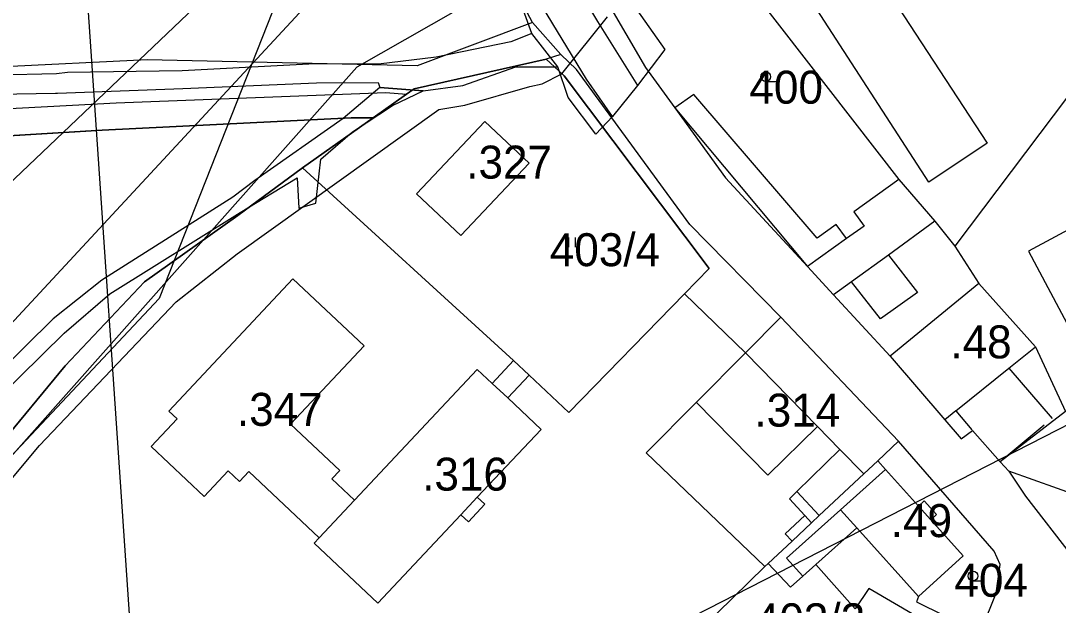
# Model space of a CAD drawing. Extents: x -564810 to -550519, y -1045831 to -1034011.
# Drawn here: x -553559.2 to -553398.7, y -1036821.1 to -1036730.6 of the extents above; entities that cross this region are included whole.
import ezdxf

# ---------------------------------------------------------------- set-up
doc = ezdxf.new("R2010")
doc.units = 0
for name, color, linetype in [('KN stav', 7, 'Continuous'), ('Obvod KPU', 7, 'Continuous'), ('Parcelní čísla', 7, 'Continuous'), ('Plynovod', 7, 'Continuous'), ('Polní cesty stavající', 7, 'Continuous'), ('STG', 7, 'Continuous'), ('Vedení VN', 7, 'Continuous'), ('Vrstva 16', 7, 'Continuous'), ('Vrstva 22', 7, 'Continuous'), ('Vrstva 39', 7, 'Continuous'), ('Vrstva 4', 7, 'Continuous'), ('zamokř ploch', 7, 'Continuous')]:
    doc.layers.add(name, color=color, linetype=linetype)

msp = doc.modelspace()

# ---------------------------------------------------------------- linework, layer by layer
at = {"layer": 'KN stav'}
for p, q in [((-553480, -1036730.9), (-553506.43, -1036681.97)), ((-553453.94, -1036715.78), (-553423.34, -1036755.23)), ((-553468.61, -1036727.47), (-553462.54, -1036737.9)), ((-553480, -1036730.9), (-553497.88, -1036737.61)), ((-553475.61, -1036735.89), (-553480, -1036730.9)), ((-553390.79, -1036733.87), (-553414.68, -1036765.53)), ((-553539.67, -1036736.67), (-553646.49, -1036742.01)), ((-553497.88, -1036737.61), (-553539.67, -1036736.67)), ((-553477.9, -1036736.58), (-553498.31, -1036741.16)), ((-553498.31, -1036741.16), (-553477.9, -1036736.58)), ((-553475.61, -1036735.89), (-553477.9, -1036736.58)), ((-553477.9, -1036736.58), (-553475.25, -1036739)), ((-553475.25, -1036739), (-553477.9, -1036736.58)), ((-553473.22, -1036738.18), (-553475.61, -1036735.89)), ((-553475.25, -1036739), (-553475.13, -1036739.16)), ((-553475.13, -1036739.16), (-553475.25, -1036739)), ((-553455.66, -1036762.18), (-553473.22, -1036738.18)), ((-553462.54, -1036737.9), (-553458, -1036744.14)), ((-553475.13, -1036739.16), (-553452.69, -1036769)), ((-553452.69, -1036769), (-553475.13, -1036739.16)), ((-553544.43, -1036743.37), (-553502.71, -1036741.75)), ((-553499.51, -1036742.01), (-553504.68, -1036745.67)), ((-553504.68, -1036745.67), (-553499.51, -1036742.01)), ((-553502.71, -1036741.75), (-553499.51, -1036742.01)), ((-553498.31, -1036741.16), (-553499.51, -1036742.01)), ((-553499.51, -1036742.01), (-553498.31, -1036741.16)), ((-553455.05, -1036742.06), (-553458, -1036744.14)), ((-553435.95, -1036764.27), (-553455.05, -1036742.06)), ((-553598.13, -1036746.15), (-553544.43, -1036743.37)), ((-553458, -1036744.14), (-553450.14, -1036754.96)), ((-553546.63, -1036747.58), (-553508.07, -1036745.65)), ((-553508.07, -1036745.65), (-553546.63, -1036747.58)), ((-553504.68, -1036745.67), (-553515.6, -1036753.41)), ((-553515.6, -1036753.41), (-553504.68, -1036745.67)), ((-553508.07, -1036745.65), (-553504.68, -1036745.67)), ((-553504.68, -1036745.67), (-553508.07, -1036745.65)), ((-553487.42, -1036746.22), (-553497.96, -1036757.4)), ((-553497.96, -1036757.4), (-553487.42, -1036746.22)), ((-553480.55, -1036752.7), (-553487.42, -1036746.22)), ((-553487.42, -1036746.22), (-553480.55, -1036752.7)), ((-553583.22, -1036749.82), (-553546.63, -1036747.58)), ((-553546.63, -1036747.58), (-553583.22, -1036749.82)), ((-553515.6, -1036753.41), (-553525.6, -1036760.76)), ((-553525.6, -1036760.76), (-553515.6, -1036753.41)), ((-553482.96, -1036783.22), (-553515.6, -1036753.41)), ((-553515.6, -1036753.41), (-553482.96, -1036783.22)), ((-553491.09, -1036763.88), (-553480.55, -1036752.7)), ((-553480.55, -1036752.7), (-553491.09, -1036763.88)), ((-553450.14, -1036754.96), (-553437.47, -1036768.69)), ((-553423.34, -1036755.23), (-553430.29, -1036760.21)), ((-553423.34, -1036755.23), (-553417.77, -1036761.65)), ((-553497.96, -1036757.4), (-553491.09, -1036763.88)), ((-553491.09, -1036763.88), (-553497.96, -1036757.4)), ((-553525.6, -1036760.76), (-553540.04, -1036771.06)), ((-553540.04, -1036771.06), (-553525.6, -1036760.76)), ((-553430.29, -1036760.21), (-553428.71, -1036762.41)), ((-553441.6, -1036776.51), (-553455.66, -1036762.18)), ((-553433.01, -1036762.16), (-553435.95, -1036764.27)), ((-553431.44, -1036764.36), (-553433.01, -1036762.16)), ((-553428.71, -1036762.41), (-553431.44, -1036764.36)), ((-553417.77, -1036761.65), (-553414.68, -1036765.53)), ((-553414.68, -1036765.53), (-553410.95, -1036771.32)), ((-553452.69, -1036769), (-553456.51, -1036772.92)), ((-553456.51, -1036772.92), (-553452.69, -1036769)), ((-553437.47, -1036768.69), (-553433.44, -1036773.06)), ((-553540.04, -1036771.06), (-553552.36, -1036784.03)), ((-553552.36, -1036784.03), (-553540.04, -1036771.06)), ((-553536.32, -1036791.05), (-553517.1, -1036770.59)), ((-553517.1, -1036770.59), (-553506.08, -1036780.94)), ((-553410.95, -1036771.32), (-553402.2, -1036781.1)), ((-553456.51, -1036772.92), (-553474.39, -1036791.27)), ((-553474.39, -1036791.27), (-553456.51, -1036772.92)), ((-553433.44, -1036773.06), (-553424.68, -1036782.56)), ((-553447.06, -1036782.01), (-553441.6, -1036776.51)), ((-553423.36, -1036795.71), (-553441.6, -1036776.51)), ((-553506.08, -1036780.94), (-553517.46, -1036793.06)), ((-553454.66, -1036789.66), (-553447.06, -1036782.01)), ((-553402.2, -1036781.1), (-553397.52, -1036791.1)), ((-553552.36, -1036784.03), (-553589.87, -1036829.38)), ((-553589.87, -1036829.38), (-553552.36, -1036784.03)), ((-553486.28, -1036786.76), (-553482.96, -1036783.22)), ((-553480.56, -1036785.48), (-553482.96, -1036783.22)), ((-553482.96, -1036783.22), (-553480.56, -1036785.48)), ((-553424.68, -1036782.56), (-553416.21, -1036792.38)), ((-553507.56, -1036804.82), (-553488.57, -1036784.61)), ((-553488.57, -1036784.61), (-553486.28, -1036786.76)), ((-553480.56, -1036785.48), (-553483.86, -1036789)), ((-553474.39, -1036791.27), (-553480.56, -1036785.48)), ((-553480.56, -1036785.48), (-553474.39, -1036791.27)), ((-553483.86, -1036789), (-553478.68, -1036793.86)), ((-553462.44, -1036797.49), (-553454.66, -1036789.66)), ((-553535.03, -1036792.26), (-553536.32, -1036791.05)), ((-553397.52, -1036791.1), (-553407.66, -1036798.87)), ((-553539.04, -1036796.54), (-553535.03, -1036792.26)), ((-553517.46, -1036793.06), (-553509.83, -1036800.24)), ((-553416.21, -1036792.38), (-553413.66, -1036795.34)), ((-553478.68, -1036793.86), (-553488.56, -1036804.37)), ((-553413.66, -1036795.34), (-553411.92, -1036794.04)), ((-553411.92, -1036794.04), (-553407.66, -1036798.87)), ((-553530.83, -1036804.25), (-553539.04, -1036796.54)), ((-553423.36, -1036795.71), (-553426.58, -1036798.72)), ((-553408.57, -1036812.73), (-553423.36, -1036795.71)), ((-553444.08, -1036815.09), (-553462.44, -1036797.49)), ((-553426.58, -1036798.72), (-553428.74, -1036800.74)), ((-553426.58, -1036798.72), (-553425.38, -1036800.05)), ((-553425.38, -1036800.05), (-553420.28, -1036805.73)), ((-553407.66, -1036798.87), (-553406.3, -1036800.33)), ((-553527.11, -1036800.3), (-553530.83, -1036804.25)), ((-553525.36, -1036801.95), (-553527.11, -1036800.3)), ((-553523.9, -1036800.4), (-553525.36, -1036801.95)), ((-553513.01, -1036810.63), (-553523.9, -1036800.4)), ((-553509.83, -1036800.24), (-553511.05, -1036801.54)), ((-553511.05, -1036801.54), (-553507.56, -1036804.82)), ((-553428.74, -1036800.74), (-553435.66, -1036807.21)), ((-553406.3, -1036800.33), (-553403.71, -1036804.22)), ((-553391.72, -1036805.55), (-553406.3, -1036800.33)), ((-553507.56, -1036804.82), (-553513.01, -1036810.63)), ((-553488.56, -1036804.37), (-553487.4, -1036805.46)), ((-553403.71, -1036804.22), (-553396.47, -1036813.58)), ((-553487.4, -1036805.46), (-553489.94, -1036808.17)), ((-553420.28, -1036805.73), (-553419.39, -1036804.94)), ((-553419.39, -1036804.94), (-553417.48, -1036807.06)), ((-553491.1, -1036807.08), (-553503.95, -1036820.76)), ((-553489.94, -1036808.17), (-553491.1, -1036807.08)), ((-553435.66, -1036807.21), (-553436.82, -1036808.3)), ((-553417.48, -1036807.06), (-553418.37, -1036807.86)), ((-553418.37, -1036807.86), (-553413.35, -1036813.45)), ((-553436.82, -1036808.3), (-553439.86, -1036811.14)), ((-553513.82, -1036811.49), (-553513.01, -1036810.63)), ((-553439.86, -1036811.14), (-553443.55, -1036814.59)), ((-553503.95, -1036820.76), (-553513.82, -1036811.49)), ((-553407.66, -1036814.79), (-553408.57, -1036812.73)), ((-553413.35, -1036813.45), (-553420.31, -1036819.7)), ((-553454.68, -1036825.42), (-553444.08, -1036815.09)), ((-553443.55, -1036814.59), (-553444.08, -1036815.09)), ((-553443.55, -1036814.59), (-553440.09, -1036818.29)), ((-553438.2, -1036816.58), (-553436.18, -1036814.77)), ((-553436.18, -1036814.77), (-553430.09, -1036821.62)), ((-553408.24, -1036819.19), (-553407.66, -1036814.79)), ((-553440.09, -1036818.29), (-553438.2, -1036816.58)), ((-553427.97, -1036818.48), (-553430.09, -1036821.62)), ((-553411.77, -1036827.9), (-553427.97, -1036818.48)), ((-553410.74, -1036825.37), (-553408.24, -1036819.19)), ((-553420.31, -1036819.7), (-553420.59, -1036820.55)), ((-553420.59, -1036820.55), (-553410.74, -1036825.37))]:
    msp.add_line(p, q, dxfattribs=at)
at = {"layer": 'Obvod KPU'}
for p, q in [((-553475.47, -1036738.86), (-553468.39, -1036730.06)), ((-553478.53, -1036740.43), (-553475.47, -1036738.86)), ((-553480.42, -1036740.83), (-553478.53, -1036740.43)), ((-553490.48, -1036743.7), (-553480.42, -1036740.83)), ((-553494.51, -1036744.4), (-553490.48, -1036743.7)), ((-553525.74, -1036766.71), (-553494.51, -1036744.4)), ((-553535.15, -1036774.13), (-553525.74, -1036766.71)), ((-553556.32, -1036796.38), (-553535.15, -1036774.13)), ((-553571.14, -1036814.01), (-553556.32, -1036796.38))]:
    msp.add_line(p, q, dxfattribs=at)
at = {"layer": 'Plynovod'}
msp.add_lwpolyline([(-554428.56, -1035578.55), (-554428.56, -1035578.55), (-554428.56, -1035578.55), (-554027.79, -1036081.22), (-553723.76, -1036467.01), (-553550.38, -1036705.78), (-553550.38, -1036705.78), (-553522.74, -1037110.43), (-553438.57, -1037242.38), (-553213.69, -1037591.73), (-553193.58, -1037703.57), (-553145.84, -1037777.72), (-553110.67, -1037838.04), (-552972.47, -1038070.52), (-552972.47, -1038070.52), (-552302.85, -1038878.56)], dxfattribs=at)
at = {"layer": 'Polní cesty stavající'}
for p, q in [((-553480.13, -1036732.61), (-553483.38, -1036733.92)), ((-553480.13, -1036732.61), (-553480.13, -1036732.61)), ((-553483.38, -1036733.92), (-553494.95, -1036736.3)), ((-553513.63, -1036737.29), (-553534.22, -1036738.39)), ((-553503.85, -1036737.36), (-553513.63, -1036737.29)), ((-553494.95, -1036736.3), (-553503.85, -1036737.36)), ((-553553.67, -1036738.87), (-553583.99, -1036739.48)), ((-553551.97, -1036738.63), (-553553.67, -1036738.87)), ((-553534.22, -1036738.39), (-553551.97, -1036738.63)), ((-553490.79, -1036740.68), (-553482.59, -1036737.77)), ((-553482.59, -1036737.77), (-553476.12, -1036737.78)), ((-553476.12, -1036737.78), (-553476.12, -1036737.78)), ((-553476.12, -1036737.78), (-553476.12, -1036737.78)), ((-553476.12, -1036737.78), (-553476.12, -1036737.78)), ((-553534.11, -1036741.13), (-553513.47, -1036740.23)), ((-553513.47, -1036740.23), (-553503.91, -1036740.21)), ((-553503.91, -1036740.21), (-553503.63, -1036740.96)), ((-553503.91, -1036740.21), (-553503.63, -1036740.96)), ((-553496.93, -1036741.51), (-553490.79, -1036740.68)), ((-553583.43, -1036742.4), (-553553.86, -1036741.87)), ((-553553.86, -1036741.87), (-553553.55, -1036741.86)), ((-553553.55, -1036741.86), (-553534.11, -1036741.13)), ((-553503.63, -1036740.96), (-553509.31, -1036745.75)), ((-553503.63, -1036740.96), (-553496.93, -1036741.51)), ((-553503.63, -1036740.96), (-553496.93, -1036741.51)), ((-553496.93, -1036741.51), (-553503.63, -1036740.96)), ((-553501.67, -1036743.78), (-553496.93, -1036741.51)), ((-553507.87, -1036747.84), (-553501.67, -1036743.78)), ((-553509.31, -1036745.75), (-553522.97, -1036755.37)), ((-553512.77, -1036752.08), (-553507.87, -1036747.84)), ((-553513.55, -1036758.86), (-553512.77, -1036752.08)), ((-553525.25, -1036760.29), (-553516.42, -1036754.93)), ((-553516.42, -1036754.93), (-553516.16, -1036759.66)), ((-553522.97, -1036755.37), (-553526.39, -1036757.95)), ((-553526.39, -1036757.95), (-553546.69, -1036770.77)), ((-553516.16, -1036759.66), (-553513.55, -1036758.86)), ((-553545.44, -1036772.89), (-553525.25, -1036760.29)), ((-553546.69, -1036770.77), (-553554.18, -1036776.78)), ((-553552.52, -1036778.98), (-553545.44, -1036772.89)), ((-553554.18, -1036776.78), (-553586.62, -1036808.64)), ((-553585.01, -1036811.02), (-553552.52, -1036778.98))]:
    msp.add_line(p, q, dxfattribs=at)
at = {"layer": 'STG'}
msp.add_lwpolyline([(-553913.89, -1037214.19), (-553796.31, -1037140.69), (-553706.3, -1037067.18), (-553629.14, -1036991.84), (-553566.68, -1036914.66), (-553476.66, -1036833.81), (-553318.67, -1036752.96), (-553234.16, -1036692.32), (-553142.31, -1036650.05), (-553048.61, -1036626.16), (-552953.09, -1036624.32), (-552903.48, -1036624.32), (-552861.23, -1036602.27), (-552798.77, -1036576.55), (-552738.15, -1036530.61), (-552646.29, -1036431.38), (-552581.99, -1036368.9), (-552545.25, -1036306.42), (-552506.67, -1036223.73), (-552482.79, -1036161.25), (-552440.54, -1036117.15)], dxfattribs=at)
at = {"layer": 'Vedení VN'}
for points in [[(-553567.53, -1034875.85), (-552617.75, -1036041.77), (-552525.91, -1036160.49), (-552512.48, -1036183.11), (-552698.29, -1036379.56), (-552912.35, -1036500.4), (-553117.93, -1036544.92), (-553344, -1036644.56), (-553507.2, -1036737.84), (-553648.49, -1036896.84), (-553694.41, -1037244.51), (-553658.38, -1037334.97)], [(-553684.52, -1037352.63), (-553725.5, -1037238.15), (-553666.15, -1036855.85), (-553493.77, -1036691.9), (-553319.98, -1036604.98), (-553120.76, -1036515.94), (-552942.02, -1036478.49), (-552709.59, -1036345.64), (-552689.1, -1036325.85), (-552549.22, -1036164.73)], [(-553294.31, -1036605.55), (-553373.57, -1036648.74), (-553451.25, -1036691.25), (-553510.82, -1036723.68), (-553562.2, -1036779.16), (-553608.71, -1036829.76), (-553656.52, -1036881.98), (-553666.45, -1036950.74), (-553677.06, -1037025.03), (-553686.97, -1037093.28), (-553698.77, -1037175.72), (-553707.94, -1037241.65), (-553688.47, -1037297.17), (-553671.53, -1037343.76)]]:
    msp.add_lwpolyline(points, dxfattribs=at)
at = {"layer": 'Vrstva 16'}
msp.add_lwpolyline([(-553156.59, -1036068.23), (-553271.19, -1036329.95), (-553326.01, -1036402.23), (-553438.12, -1036581.7), (-553500.41, -1036678.91), (-553537.78, -1036773.63), (-553654.88, -1036898.25), (-553794.4, -1036983), (-553946.38, -1037072.73), (-554030.85, -1037138.79), (-554140.47, -1037236), (-554172.86, -1037275.88), (-554409.55, -1037435.4), (-554469.35, -1037482.76), (-554516.68, -1037530.12), (-554559.04, -1037579.97), (-554569, -1037664.72), (-554661.19, -1037749.47), (-554907.84, -1037851.66), (-555066.31, -1037953.36)], dxfattribs=at)
at = {"layer": 'Vrstva 39'}
for p, q in [((-553471.76, -1036727.76), (-553469.95, -1036730.76)), ((-553471.64, -1036739.69), (-553478.49, -1036728.5)), ((-553469.95, -1036730.76), (-553463.79, -1036740.64)), ((-553467.64, -1036745.47), (-553471.64, -1036739.69)), ((-553463.79, -1036740.64), (-553467.64, -1036745.47)), ((-553463.79, -1036740.64), (-553467.64, -1036745.47))]:
    msp.add_line(p, q, dxfattribs=at)
for points in [[(-553467.64, -1036745.47), (-553470.22, -1036748.21), (-553474.48, -1036742.54), (-553476.12, -1036737.78), (-553480.13, -1036732.61), (-553483.22, -1036724.01), (-553493.2, -1036708.26), (-553511.64, -1036672.9), (-553519.18, -1036659.44), (-553527.92, -1036645.21), (-553541.11, -1036627.36), (-553580.33, -1036577.6)], [(-553539.38, -1036609.38), (-553526.14, -1036626.63), (-553521.25, -1036633.8), (-553493.89, -1036678.59), (-553487.9, -1036690.23), (-553478.76, -1036707.48), (-553477.49, -1036709.63), (-553459.52, -1036735.09), (-553463.79, -1036740.64), (-553467.64, -1036745.47)]]:
    msp.add_lwpolyline(points, dxfattribs=at)
at = {"layer": 'Vrstva 4'}
for p, q in [((-553438.33, -1036705.77), (-553409.64, -1036749.59)), ((-553418.66, -1036755.64), (-553447.13, -1036711.66)), ((-553458.01, -1036744.14), (-553437.47, -1036768.69)), ((-553409.64, -1036749.59), (-553418.66, -1036755.64)), ((-553391.75, -1036760.13), (-553403.24, -1036766.27)), ((-553417.77, -1036761.65), (-553424.92, -1036766.92)), ((-553431.44, -1036764.36), (-553437.47, -1036768.69)), ((-553403.24, -1036766.27), (-553396.86, -1036778.29)), ((-553424.92, -1036766.92), (-553430.64, -1036771.04)), ((-553424.92, -1036766.92), (-553420.44, -1036772.68)), ((-553430.64, -1036771.04), (-553433.44, -1036773.06)), ((-553426.19, -1036776.76), (-553430.64, -1036771.04)), ((-553420.44, -1036772.68), (-553426.19, -1036776.76)), ((-553410.95, -1036771.32), (-553424.68, -1036782.56)), ((-553456.51, -1036772.92), (-553447.06, -1036782)), ((-553447.06, -1036782), (-553435.89, -1036793.43)), ((-553406.29, -1036784.4), (-553402.2, -1036781.1)), ((-553414.52, -1036791.02), (-553406.29, -1036784.4)), ((-553406.29, -1036784.39), (-553399.58, -1036792.18)), ((-553486.28, -1036786.76), (-553483.86, -1036788.99)), ((-553443.6, -1036800.97), (-553454.67, -1036789.66)), ((-553414.52, -1036791.02), (-553416.21, -1036792.38)), ((-553414.52, -1036791.02), (-553412.02, -1036793.92)), ((-553435.89, -1036793.43), (-553443.6, -1036800.97)), ((-553435.89, -1036793.43), (-553432.44, -1036796.96)), ((-553400.83, -1036793.21), (-553407.66, -1036798.87)), ((-553432.44, -1036796.96), (-553439.13, -1036803.5)), ((-553432.44, -1036796.96), (-553428.74, -1036800.74)), ((-553432.34, -1036806.3), (-553425.38, -1036800.05)), ((-553488.56, -1036804.37), (-553491.1, -1036807.08)), ((-553439.13, -1036803.5), (-553440.27, -1036804.61)), ((-553437.87, -1036807.18), (-553440.27, -1036804.61)), ((-553435.66, -1036807.21), (-553439.13, -1036803.5)), ((-553432.34, -1036806.3), (-553440.7, -1036813.8)), ((-553432.34, -1036806.3), (-553429.84, -1036809.08)), ((-553420.28, -1036805.73), (-553418.37, -1036807.85)), ((-553440.9, -1036810.02), (-553437.87, -1036807.18)), ((-553437.87, -1036807.18), (-553436.82, -1036808.3)), ((-553429.84, -1036809.08), (-553436.18, -1036814.77)), ((-553420.31, -1036819.7), (-553429.84, -1036809.08)), ((-553439.86, -1036811.14), (-553440.9, -1036810.02)), ((-553438.2, -1036816.58), (-553440.7, -1036813.8)), ((-553420.31, -1036819.7), (-553420.59, -1036820.55))]:
    msp.add_line(p, q, dxfattribs=at)
at = {"layer": 'zamokř ploch'}
for p, q in [((-553443.92, -1036740.05), (-553442.32, -1036740.05)), ((-553474.43, -1036764.18), (-553474.43, -1036765.68)), ((-553473.43, -1036764.18), (-553473.43, -1036765.68)), ((-553411.84, -1036817.3), (-553410.24, -1036817.3))]:
    msp.add_line(p, q, dxfattribs=at)
for centre in [(-553443.92, -1036739.3), (-553411.84, -1036816.55)]:
    msp.add_circle(centre, 0.75, dxfattribs=at)

# ---------------------------------------------------------------- texts
at = {"layer": 'Parcelní čísla'}
for s, p in [('400', (-553446.45, -1036743.48)), ('403/4', (-553477.34, -1036768.62)), ('404', (-553414.73, -1036819.76)), ('403/2', (-553445.61, -1036825.88))]:
    msp.add_text(s, height=5.1, dxfattribs=at).set_placement(p)
at = {"layer": 'Vrstva 22'}
for s, p in [('.327', (-553490.27, -1036755.07)), ('.48', (-553415.35, -1036782.88)), ('.347', (-553525.76, -1036793.32)), ('.314', (-553445.67, -1036793.44)), ('.316', (-553497.09, -1036803.34)), ('.49', (-553424.57, -1036810.53))]:
    msp.add_text(s, height=5.1, dxfattribs=at).set_placement(p)

doc.saveas('drawing.dxf')
